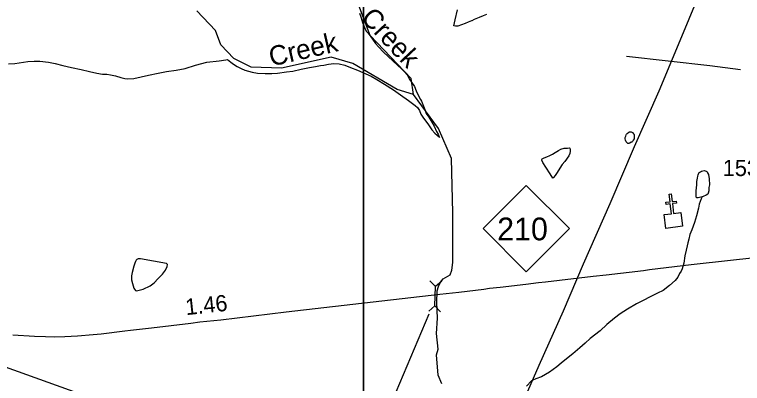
# Model space of a CAD drawing. Extents: x 2082433 to 2279600, y 546599 to 755198.
# Drawn here: x 2100738 to 2106345, y 643052 to 645891 of the extents above; entities that cross this region are included whole.
import ezdxf

# ---------------------------------------------------------------- set-up
doc = ezdxf.new("R2010")
doc.units = 0
for name, color, linetype in [('Exist Boundary Political Fire Districts', 7, 'Continuous'), ('Exist Cultural Church CELL', 7, 'Continuous'), ('Exist Hydrographic Creek Single Shore', 7, 'Continuous'), ('Exist Hydrographic Creek Single Shore Label', 7, 'Continuous'), ('Exist Hydrographic Misc Water Feature', 7, 'Continuous'), ('Exist Hydrographic Pond Under 1500 Sq Ft', 7, 'Continuous'), ('Exist Road Non-System Type 51', 7, 'Continuous'), ('Exist Road Primary NC Attributed', 7, 'Continuous'), ('Exist Road Primary NC Service Mileage Hundredths English Label', 7, 'Continuous'), ('Exist Road Primary NC Shield CELL', 7, 'Continuous'), ('Exist Road Primary NC Shield Number Label', 7, 'Continuous'), ('Exist Road Primary NC Structure Culvert CELL', 7, 'Continuous'), ('Exist Road Primary NC Structure Culvert Number Label', 7, 'Continuous'), ('Exist Road Secondary Type 51 Number Label', 7, 'Continuous'), ('Exist Utilities Electrical Transmission Line', 7, 'Continuous'), ('Map Preparation Inset Cut Line', 7, 'Continuous')]:
    doc.layers.add(name, color=color, linetype=linetype)

msp = doc.modelspace()

# ---------------------------------------------------------------- linework, layer by layer
at = {"layer": 'Exist Boundary Political Fire Districts'}
msp.add_lwpolyline([(2117062.3, 637293.1), (2099744.2, 643507.5)], dxfattribs=at)
at = {"layer": 'Exist Cultural Church CELL'}
msp.add_lwpolyline([(2105742.3, 644351.4), (2105798.8, 644358.4), (2105789.5, 644434), (2105757.8, 644430.1), (2105755.8, 644446), (2105787.6, 644449.9), (2105780.3, 644509.6), (2105796.2, 644511.5), (2105803.5, 644451.8), (2105835.3, 644455.7), (2105837.2, 644439.8), (2105805.4, 644436), (2105814.7, 644360.4), (2105871.9, 644367.3), (2105884.9, 644261.6), (2105755.2, 644245.7)], close=True, dxfattribs=at)
at = {"layer": 'Exist Hydrographic Creek Single Shore'}
for points in [[(2103811.5, 645274.5), (2103794.5, 645399.5), (2103477.5, 645730.8), (2103317.6, 646153.9), (2103300.6, 646397), (2103216.5, 646611.9), (2103198.5, 646986.3), (2103089.6, 647172.2), (2103097.6, 647211.4)], [(2103811.5, 645274.5), (2103686.4, 645313.1), (2103344.4, 645513.7), (2103177.5, 645562.9), (2102794.5, 645478.9), (2102561.5, 645486.9), (2102427.4, 645552), (2102327.4, 645658.9), (2102285.5, 645768.1), (2102143.4, 645918.6)], [(2104028.7, 643048.1), (2104001.3, 643116.6), (2103987.6, 643272), (2104001.4, 643315.4), (2103987.6, 643436.5), (2103996.8, 643555.3), (2103991.8, 643675.4), (2103993.9, 643765.3), (2104002.9, 643797.1), (2104018.1, 643831.7), (2104040.9, 643856.6), (2104074.8, 643877.4), (2104094.2, 643888.4), (2104105.9, 643925.1), (2104115.6, 643981.8), (2104114.4, 644366.2), (2104104.3, 644783), (2104004.5, 645014.7), (2103811.5, 645274.5)]]:
    msp.add_lwpolyline(points, dxfattribs=at)
at = {"layer": 'Exist Hydrographic Misc Water Feature'}
for points in [[(2103396.2, 645900.8), (2103406, 645872.9), (2103412.4, 645848.9), (2103418.3, 645828.9), (2103428.4, 645805.1), (2103438.4, 645779.2), (2103448.7, 645761.1), (2103460.8, 645749.1), (2103478.8, 645727.3), (2103500.8, 645693.6), (2103518.8, 645667.3), (2103540.9, 645641.7), (2103580.9, 645601.5), (2103617, 645567.7), (2103653.1, 645533.8), (2103691.2, 645500.1), (2103715.2, 645476.1), (2103737.6, 645454.1), (2103765.3, 645424.3), (2103781.7, 645392.3), (2103795.8, 645370.3), (2103817.8, 645338.5), (2103831.9, 645304.3), (2103848.1, 645270.7), (2103864.1, 645236.6), (2103872.3, 645224.4), (2103898.1, 645160.9), (2103910.2, 645128.7), (2103928.5, 645100.7), (2103952.9, 645063), (2103970.9, 645031.1), (2103989, 644991), (2104000.9, 644970.9), (2104008.9, 644949.3), (2104013.2, 644945.1)], [(2104373.7, 645891.9), (2104348.2, 645882), (2104316, 645867.8), (2104277.7, 645851.7), (2104261.9, 645841.5), (2104258.2, 645841.7), (2104232.2, 645831.4), (2104208.2, 645821.7), (2104180.5, 645811.3), (2104152, 645801.4), (2104136.2, 645801.3), (2104122.1, 645803.1), (2104131.9, 645849.4), (2104150.2, 645927.4)], [(2100692.2, 645510.5), (2100739.9, 645514.6), (2100773.8, 645518.8), (2100840.2, 645529), (2100888, 645533.1), (2100931.9, 645531.3), (2100999.9, 645523.5), (2101050.2, 645513.9), (2101109.8, 645497.9), (2101176.1, 645484.2), (2101249.9, 645468.2), (2101314.1, 645452.4), (2101372.1, 645438.8), (2101416.2, 645432.9), (2101448, 645432.9), (2101478.1, 645427.2), (2101516.5, 645419.3), (2101556.5, 645407.2), (2101588.2, 645399.5), (2101610, 645397.4), (2101656.1, 645397.8), (2101770.1, 645423.9), (2101843.7, 645440.3), (2101907.9, 645452.5), (2101981.7, 645462.8), (2102051.9, 645476.9), (2102131.4, 645501), (2102219.8, 645523.3), (2102313.7, 645533.8), (2102365.2, 645541.8), (2102379.5, 645545.8)], [(2102379.5, 645545.8), (2102403.9, 645523.8), (2102423.6, 645509.9), (2102453.8, 645491.9), (2102483.9, 645476), (2102511.8, 645462.5), (2102567.8, 645446.7), (2102609.8, 645440.8), (2102667.8, 645436.8), (2102719.7, 645437.1), (2102763.6, 645441), (2102831.9, 645449.3), (2102881.7, 645455.5), (2102945.7, 645471.8), (2103009.2, 645484.1), (2103055.4, 645492.1), (2103093.7, 645498.1), (2103119.4, 645502.3), (2103157.3, 645510.3), (2103197.5, 645514.4), (2103237.7, 645512.4), (2103283.2, 645500.6), (2103325.4, 645482.8), (2103379.4, 645462.9), (2103443.8, 645435.3), (2103485.8, 645415.6), (2103527.8, 645391.4), (2103587.7, 645355.6), (2103656, 645311.9), (2103711.8, 645274.3), (2103772, 645230.3), (2103824.1, 645190.4), (2103842.2, 645174.6), (2103858.6, 645152.7), (2103868.4, 645124.5), (2103888.5, 645094.6), (2103920.7, 645048.8), (2103952.7, 645003), (2103975, 644978.9), (2103994.9, 644962.9), (2104008.9, 644949.3), (2104013.2, 644945.1)], [(2105452.6, 644969.7), (2105458.4, 644975.8), (2105470.7, 644985.7), (2105474.4, 644987.5), (2105484.4, 644987.6), (2105488.3, 644987.8), (2105492.2, 644985.6), (2105498.4, 644983.9), (2105502.3, 644979.6), (2105506.4, 644973.7), (2105510.5, 644967.8), (2105512.5, 644959.9), (2105512.3, 644945.7), (2105510.7, 644935.8), (2105504.9, 644923.7), (2105498.6, 644913.7), (2105492.8, 644909.7), (2105488.7, 644907.9), (2105478.7, 644901.7), (2105470.7, 644899.7), (2105462.7, 644899.7), (2105457, 644903.8), (2105450.6, 644911.7), (2105444.4, 644923.5), (2105442.8, 644933.5), (2105442.8, 644943.7), (2105446.5, 644955.6), (2105450.2, 644965.6), (2105452.6, 644969.7)], [(2104861.3, 644805.8), (2104881.2, 644815.8), (2104901.5, 644829.7), (2104928.9, 644844.2), (2104947, 644856.1), (2104973, 644862.2), (2104997, 644862.3), (2105010.8, 644864.2), (2105016.9, 644862.1), (2105019.2, 644852.5), (2105018.8, 644840.4), (2105015.3, 644822.2), (2105007.3, 644804.4), (2104976.9, 644760.3), (2104957.7, 644736), (2104914, 644668), (2104903.7, 644652.2), (2104889.8, 644638), (2104883.8, 644632), (2104863.9, 644665.9), (2104831.3, 644717.8), (2104807.6, 644753.5), (2104799.1, 644769.8), (2104799.4, 644775.8), (2104803.2, 644781.7), (2104817, 644787.8), (2104839.1, 644795.8), (2104861.3, 644805.8)], [(2106034, 644489.5), (2106004.2, 644481.5), (2105994, 644481.4), (2105987.8, 644485.6), (2105988.2, 644495.3), (2105987.8, 644513.6), (2105989.7, 644537.6), (2105991.9, 644555.5), (2105993.6, 644583.3), (2105995.4, 644605.3), (2105999.3, 644631.5), (2106001.2, 644647.4), (2106003.4, 644657.6), (2106009.2, 644669.3), (2106013.1, 644675.6), (2106023.1, 644681.4), (2106030.9, 644685.5), (2106039.3, 644689.5), (2106051.2, 644691.7), (2106064.9, 644685.6), (2106071.5, 644683.8), (2106077.4, 644673.6), (2106083.2, 644659.7), (2106089.3, 644628), (2106091.4, 644581.8), (2106087.7, 644559.7), (2106085.4, 644535.7), (2106081.5, 644517.6), (2106077.6, 644509.7), (2106065.8, 644501.8), (2106044, 644491.7), (2106034, 644489.5)], [(2106034, 644489.5), (2106028, 644471.8), (2106012, 644431.6), (2106006.1, 644401.7), (2105990.3, 644341.6), (2105976.3, 644291.4), (2105954.6, 644235.5), (2105940.7, 644199.5), (2105932.9, 644163.3), (2105924.9, 644135.4), (2105919.1, 644111.5), (2105913, 644077.5), (2105902.9, 644035.2), (2105893.3, 643977.5), (2105881.6, 643935.5), (2105873.6, 643917.2), (2105861.7, 643897.1), (2105848, 643871.2), (2105827.9, 643845), (2105783.8, 643807.1), (2105734, 643768.8), (2105690.1, 643746.7), (2105634.3, 643718.6), (2105580.4, 643690.3), (2105528.3, 643664.5), (2105458.8, 643623.9), (2105404.7, 643587.9), (2105361, 643555.6), (2105301.3, 643505.4), (2105249, 643457.3), (2105171.3, 643399.4), (2105133.6, 643363.3), (2105093.6, 643325.2), (2105037.6, 643280.9), (2104989.6, 643242.7), (2104948.2, 643208.5), (2104916.4, 643180.4), (2104858.2, 643140.2), (2104796.5, 643104.1), (2104752.6, 643088), (2104730.7, 643077.9), (2104720.6, 643071.8), (2104682.5, 643031.7)]]:
    msp.add_lwpolyline(points, dxfattribs=at)
at = {"layer": 'Exist Hydrographic Pond Under 1500 Sq Ft'}
msp.add_lwpolyline([(2101909.6, 643975.3), (2101707.6, 644010.8), (2101691.4, 644010.8), (2101679.3, 644006.6), (2101675.2, 644000.7), (2101669.4, 643990.6), (2101665.1, 643978.7), (2101657.4, 643954.7), (2101643.4, 643906.5), (2101637.9, 643880.6), (2101639.7, 643848.7), (2101645.7, 643820.6), (2101652, 643804.6), (2101658, 643784.7), (2101661.9, 643776.8), (2101670.3, 643768.7), (2101676.4, 643764.9), (2101698.4, 643768.9), (2101728.1, 643779), (2101781.8, 643803.3), (2101812.2, 643827), (2101843.3, 643859.2), (2101877.6, 643893.4), (2101901.4, 643923.5), (2101913.7, 643951.6), (2101915.5, 643967.6), (2101909.6, 643975.3)], dxfattribs=at)
at = {"layer": 'Exist Road Non-System Type 51'}
msp.add_lwpolyline([(2106331.6, 645465.8), (2106093.1, 645497.3), (2105453.4, 645568.1)], dxfattribs=at)
at = {"layer": 'Exist Road Primary NC Attributed'}
msp.add_lwpolyline([(2100723.8, 643426.7), (2100891.6, 643416.2), (2100976.1, 643412.9), (2101044, 643412.1), (2101124.2, 643412.9), (2101221.7, 643419.6), (2101344.7, 643429.3), (2101405.5, 643435.2), (2101588.2, 643456.1), (2101631.7, 643461.7), (2101793.4, 643480.7), (2102095.5, 643517.3), (2102165, 643525.8), (2102327.4, 643543), (2102830.7, 643602.7), (2104013.7, 643739.8), (2104160.4, 643756), (2104352.4, 643778), (2104396.1, 643784.4), (2104478.2, 643793.7), (2104677, 643816.8), (2104775.4, 643828), (2104829, 643833.6), (2105195.7, 643877.6), (2105295.7, 643888.5), (2105582.4, 643922.4), (2105628.7, 643928), (2105950.2, 643966.8), (2106253.4, 644001.4), (2106416.8, 644020.1)], dxfattribs=at)
at = {"layer": 'Exist Road Primary NC Shield CELL'}
msp.add_lwpolyline([(2104347, 644243.4), (2104680, 644576.4), (2105013, 644243.4), (2104680, 643910.4)], close=True, dxfattribs=at)
at = {"layer": 'Exist Road Primary NC Structure Culvert CELL'}
for p, q in [((2103937.9, 643841.8), (2103981.6, 643797.2)), ((2104028.6, 643838.3), (2103981.6, 643797.2)), ((2103975.8, 643648.5), (2103981.6, 643797.2)), ((2103928.8, 643607.3), (2103975.8, 643648.5)), ((2104019.5, 643603.8), (2103975.8, 643648.5))]:
    msp.add_line(p, q, dxfattribs=at)
at = {"layer": 'Exist Road Primary NC Structure Culvert Number Label'}
msp.add_line((2103928.5, 643586.5), (2103054.3, 641517.1), dxfattribs=at)
at = {"layer": 'Exist Utilities Electrical Transmission Line'}
msp.add_lwpolyline([(2102025.4, 637138.5), (2102238.9, 637532.5), (2102382.6, 637760.1), (2102580.1, 638166.9), (2102752.8, 638567.4), (2102947.3, 639003.8), (2103126.1, 639424.4), (2103302.7, 639830.8), (2103493.3, 640263.3), (2103670.2, 640659.6), (2103856.7, 641104.2), (2104043.3, 641528.6), (2104224, 641937.1), (2104406.7, 642353.6), (2104595.4, 642770.1), (2104780, 643192.5), (2104966.7, 643610.9), (2105121.6, 643973.3), (2105326.1, 644437.9), (2105514.6, 644876.3), (2105703.3, 645302.8), (2105878, 645721.2), (2106048.8, 646131.7)], dxfattribs=at)
at = {"layer": 'Map Preparation Inset Cut Line'}
for points in [[(2115667.4, 674476.7), (2179108.5, 674476.7), (2179108.5, 645771.4), (2163899.7, 645768.1), (2163899.7, 630228.2), (2103425.3, 630228.2), (2103425.3, 662094.1)], [(2103425.3, 630228.2), (2082433, 644416.2), (2103425.3, 662094.1)]]:
    msp.add_lwpolyline(points, close=True, dxfattribs=at)

# ---------------------------------------------------------------- texts
at = {"layer": 'Exist Hydrographic Creek Single Shore Label'}
for rotation, p in [(313.1721, (2103398.9, 645858.8)), (12.9093, (2102716.8, 645490.8))]:
    msp.add_text('Creek', height=150, rotation=rotation, dxfattribs=at).set_placement(p)
at = {"layer": 'Exist Road Primary NC Service Mileage Hundredths English Label'}
msp.add_text('1.46', height=125, rotation=6.0395, dxfattribs=at).set_placement((2102059.9, 643577.6))
at = {"layer": 'Exist Road Primary NC Shield Number Label'}
msp.add_text('210', height=175, dxfattribs=at).set_placement((2104456.1, 644153.7))
at = {"layer": 'Exist Road Secondary Type 51 Number Label'}
msp.add_text('1539', height=125, dxfattribs=at).set_placement((2106193.8, 644648))

doc.saveas('drawing.dxf')
